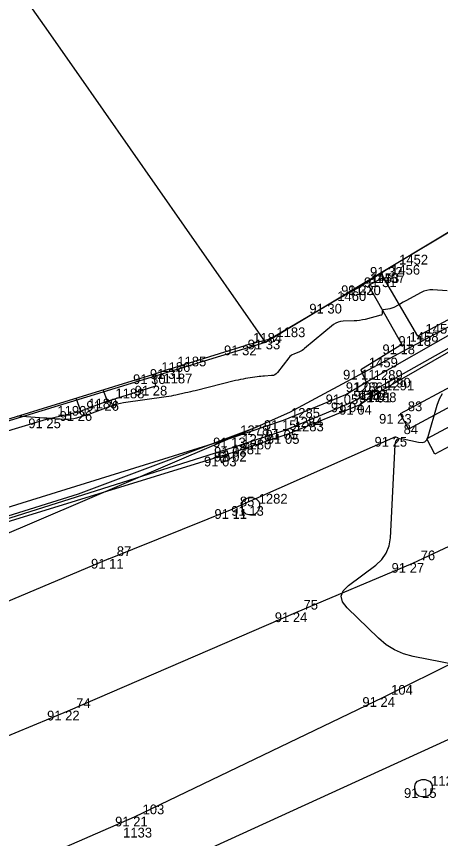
# Model space of a CAD drawing. Extents: x -711081 to -709338, y -1025122 to -1024092.
# Drawn here: x -710971.31 to -710959.11, y -1025043.88 to -1025020.22 of the extents above; entities that cross this region are included whole.
import ezdxf

# ---------------------------------------------------------------- set-up
doc = ezdxf.new("R2010")
doc.units = 0
for name, color, linetype in [('Ex_Minor Contours', 7, 'Continuous'), ('Z_anglicke_dvorky', 7, 'Continuous'), ('Z_body', 7, 'Continuous'), ('Z_body_cisla', 7, 'Continuous'), ('Z_body_vysky_redukovane', 7, 'Continuous'), ('Z_budova', 7, 'Continuous'), ('Z_katastr_hranice', 7, 'Continuous'), ('Z_komunikace', 7, 'Continuous'), ('Z_obruba', 7, 'Continuous'), ('Z_rozhranni', 7, 'Continuous'), ('Z_site_kanalizace_znaky', 7, 'Continuous'), ('Z_vdz12_plna', 7, 'Continuous'), ('Z_vdz12_prerusovana', 7, 'Continuous'), ('Z_vdz25_plna', 7, 'Continuous'), ('Z_vdz25_prerusovana', 7, 'Continuous'), ('Z_vdz_prechod', 7, 'Continuous'), ('Z_vstupy', 7, 'Continuous')]:
    doc.layers.add(name, color=color, linetype=linetype)

# ---------------------------------------------------------------- blocks, each defined once
blk = doc.blocks.new('POINT_DISPLAY')
blk.add_line((0, 0), (0, 0))
blk = doc.blocks.new('Z620')
for p, q in [((-0.17, 0.2), (-0.05, 0.25)), ((-0.05, 0.25), (0.05, 0.25)), ((0.05, 0.25), (0.17, 0.2)), ((-0.25, 0.05), (-0.23, 0.13)), ((-0.25, -0.05), (-0.25, 0.05)), ((-0.23, 0.13), (-0.17, 0.2)), ((0.17, 0.2), (0.23, 0.13)), ((0.23, 0.13), (0.25, 0.05)), ((0.25, 0.05), (0.25, -0.05)), ((-0.2, -0.17), (-0.25, -0.05)), ((-0.13, -0.23), (-0.2, -0.17)), ((-0.05, -0.25), (-0.13, -0.23)), ((0.13, -0.23), (0.05, -0.25)), ((0.2, -0.17), (0.13, -0.23)), ((0.25, -0.05), (0.2, -0.17)), ((0.05, -0.25), (-0.05, -0.25))]:
    blk.add_line(p, q)
blk = doc.blocks.new('Z46260')
for p, q in [((0.13, 0.13), (-0.13, 0.13)), ((-0.13, 0.13), (-0.13, -0.13)), ((0.13, 0), (-0.13, 0)), ((0.13, -0.13), (0.13, 0.13)), ((-0.13, -0.13), (0.13, -0.13))]:
    blk.add_line(p, q)

msp = doc.modelspace()

# ---------------------------------------------------------------- linework, layer by layer
at = {"layer": 'Ex_Minor Contours'}
for points in [[(-710958.915, -1025028.118), (-710959.33, -1025028.091), (-710959.418, -1025028.092), (-710959.505, -1025028.104), (-710959.588, -1025028.129), (-710959.669, -1025028.166), (-710960.107, -1025028.405), (-710960.126, -1025028.415), (-710960.145, -1025028.425), (-710960.163, -1025028.436), (-710960.182, -1025028.446), (-710960.256, -1025028.489), (-710960.275, -1025028.499), (-710960.293, -1025028.51), (-710960.312, -1025028.52), (-710960.331, -1025028.53), (-710960.452, -1025028.593), (-710960.479, -1025028.606), (-710960.507, -1025028.616), (-710960.535, -1025028.625), (-710960.564, -1025028.631), (-710960.745, -1025028.662), (-710960.76, -1025028.667), (-710960.772, -1025028.676), (-710960.779, -1025028.688), (-710960.783, -1025028.704), (-710960.788, -1025028.775), (-710960.791, -1025028.791), (-710960.798, -1025028.803), (-710960.809, -1025028.813), (-710960.824, -1025028.819), (-710961.281, -1025028.938), (-710961.357, -1025028.955), (-710961.435, -1025028.968), (-710961.512, -1025028.977), (-710961.591, -1025028.981), (-710961.906, -1025028.987), (-710961.982, -1025028.995), (-710962.054, -1025029.014), (-710962.122, -1025029.046), (-710962.185, -1025029.09), (-710963.018, -1025029.78), (-710963.053, -1025029.807), (-710963.09, -1025029.831), (-710963.128, -1025029.852), (-710963.169, -1025029.87), (-710963.333, -1025029.938), (-710963.373, -1025029.957), (-710963.409, -1025029.981), (-710963.441, -1025030.009), (-710963.47, -1025030.042), (-710963.8, -1025030.469), (-710963.834, -1025030.505), (-710963.873, -1025030.532), (-710963.918, -1025030.549), (-710963.967, -1025030.557), (-710964.174, -1025030.569), (-710964.225, -1025030.573), (-710964.277, -1025030.578), (-710964.328, -1025030.584), (-710964.379, -1025030.591), (-710964.716, -1025030.644), (-710964.789, -1025030.656), (-710964.862, -1025030.67), (-710964.934, -1025030.685), (-710965.006, -1025030.702), (-710966.166, -1025030.992), (-710966.235, -1025031.009), (-710966.304, -1025031.026), (-710966.373, -1025031.042), (-710966.442, -1025031.057), (-710966.719, -1025031.118), (-710966.789, -1025031.132), (-710966.858, -1025031.145), (-710966.928, -1025031.157), (-710966.999, -1025031.168), (-710968.225, -1025031.344), (-710968.318, -1025031.36), (-710968.411, -1025031.381), (-710968.501, -1025031.407), (-710968.591, -1025031.438), (-710968.974, -1025031.582), (-710969.049, -1025031.61), (-710969.125, -1025031.636), (-710969.2, -1025031.662), (-710969.276, -1025031.686), (-710969.584, -1025031.781), (-710969.659, -1025031.801), (-710969.736, -1025031.814), (-710969.813, -1025031.819), (-710969.89, -1025031.818), (-710970.203, -1025031.799), (-710970.282, -1025031.795), (-710970.36, -1025031.79), (-710970.438, -1025031.785), (-710970.516, -1025031.779), (-710971.27, -1025031.727)], [(-710956.605, -1025039.281), (-710959.896, -1025038.636), (-710960.174, -1025038.561), (-710960.432, -1025038.45), (-710960.67, -1025038.302), (-710960.89, -1025038.117), (-710961.797, -1025037.239), (-710961.927, -1025037.071), (-710961.963, -1025036.908), (-710961.907, -1025036.752), (-710961.756, -1025036.601), (-710960.969, -1025036.011), (-710960.796, -1025035.851), (-710960.668, -1025035.667), (-710960.586, -1025035.458), (-710960.55, -1025035.224), (-710960.412, -1025032.545), (-710960.393, -1025032.45), (-710960.348, -1025032.389), (-710960.277, -1025032.363), (-710960.18, -1025032.372), (-710959.741, -1025032.476), (-710959.641, -1025032.486), (-710959.561, -1025032.461), (-710959.501, -1025032.403), (-710959.461, -1025032.311), (-710959.208, -1025031.405), (-710959.142, -1025031.227), (-710959.049, -1025031.069)]]:
    msp.add_lwpolyline(points, dxfattribs=at)
at = {"layer": 'Z_anglicke_dvorky'}
for p, q in [((-710968.69, -1025031.29), (-710968.818, -1025030.968)), ((-710969.46, -1025031.58), (-710969.587, -1025031.206)), ((-710968.69, -1025031.29), (-710969.46, -1025031.58))]:
    msp.add_line(p, q, dxfattribs=at)
at = {"layer": 'Z_budova'}
for p, q in [((-710951.7, -1025022.12), (-710960.53, -1025027.43)), ((-710960.53, -1025027.43), (-710961.36, -1025027.96)), ((-710964.05, -1025029.52), (-710962.3, -1025028.49)), ((-710964.05, -1025029.52), (-710964.73, -1025029.69)), ((-710966.91, -1025030.37), (-710967.37, -1025030.52)), ((-710967.37, -1025030.52), (-710972.83, -1025032.21))]:
    msp.add_line(p, q, dxfattribs=at)
at = {"layer": 'Z_katastr_hranice'}
for p, q in [((-710970.5, -1025020.49), (-710976.09, -1025012.49)), ((-710969.58, -1025021.8), (-710970.5, -1025020.49)), ((-710964.14, -1025029.59), (-710969.58, -1025021.8)), ((-710964.14, -1025029.59), (-710951.03, -1025021.69)), ((-710955.17, -1025027.15), (-710963.45, -1025031.62)), ((-710979.94, -1025034.42), (-710964.14, -1025029.59)), ((-710963.45, -1025031.62), (-710964.38, -1025032.03)), ((-710964.38, -1025032.03), (-710987.15, -1025041.75)), ((-710969.52, -1025033.96), (-710964.38, -1025032.03)), ((-710998.91, -1025043.08), (-710969.52, -1025033.96)), ((-710988.36, -1025054.5), (-710954.66, -1025039.09))]:
    msp.add_line(p, q, dxfattribs=at)
at = {"layer": 'Z_komunikace'}
for p, q in [((-710961.03, -1025030.98), (-710958.07, -1025029.31)), ((-710961.68, -1025031.33), (-710961.03, -1025030.98)), ((-710963.56, -1025032.12), (-710961.68, -1025031.33)), ((-710965.04, -1025032.61), (-710963.56, -1025032.12)), ((-710972.93, -1025035.1), (-710965.04, -1025032.61))]:
    msp.add_line(p, q, dxfattribs=at)
at = {"layer": 'Z_obruba'}
for p, q in [((-710961.25, -1025030.75), (-710958.28, -1025029.05)), ((-710961.83, -1025031.1), (-710961.25, -1025030.75)), ((-710963.63, -1025031.84), (-710961.83, -1025031.1)), ((-710965.09, -1025032.34), (-710963.63, -1025031.84)), ((-710973.02, -1025034.8), (-710965.09, -1025032.34))]:
    msp.add_line(p, q, dxfattribs=at)
at = {"layer": 'Z_rozhranni'}
for p, q in [((-710960.75, -1025027.73), (-710961.18, -1025027.96)), ((-710959.76, -1025029.42), (-710960.75, -1025027.73)), ((-710961.18, -1025027.96), (-710960.22, -1025029.66)), ((-710958.49, -1025028.73), (-710959.76, -1025029.42)), ((-710960.92, -1025031.05), (-710958.02, -1025029.38)), ((-710960.22, -1025029.66), (-710961.4, -1025030.39)), ((-710961.4, -1025030.39), (-710961.25, -1025030.75)), ((-710967.3, -1025030.85), (-710967.37, -1025030.52)), ((-710968.69, -1025031.29), (-710967.3, -1025030.85)), ((-710961.44, -1025031.4), (-710960.92, -1025031.05)), ((-710970.36, -1025031.79), (-710969.46, -1025031.58)), ((-710963.52, -1025032.24), (-710961.44, -1025031.4)), ((-710970.36, -1025031.79), (-710974.78, -1025033.12)), ((-710965.04, -1025032.75), (-710963.52, -1025032.24)), ((-710972.94, -1025035.19), (-710965.04, -1025032.75))]:
    msp.add_line(p, q, dxfattribs=at)
at = {"layer": 'Z_vdz12_plna'}
for p, q in [((-710959.91, -1025035.95), (-710957.65, -1025034.9)), ((-710963.27, -1025037.37), (-710959.91, -1025035.95))]:
    msp.add_line(p, q, dxfattribs=at)
at = {"layer": 'Z_vdz12_prerusovana'}
for p, q in [((-710969.82, -1025040.2), (-710963.27, -1025037.37)), ((-710974.72, -1025042.24), (-710969.82, -1025040.2))]:
    msp.add_line(p, q, dxfattribs=at)
at = {"layer": 'Z_vdz25_plna'}
msp.add_line((-710960.4, -1025032.32), (-710965.1, -1025034.4), dxfattribs=at)
at = {"layer": 'Z_vdz25_prerusovana'}
for p, q in [((-710968.65, -1025035.83), (-710965.1, -1025034.4)), ((-710968.65, -1025035.83), (-710975.94, -1025038.9)), ((-710960.75, -1025039.81), (-710955.82, -1025037.36)), ((-710967.91, -1025043.25), (-710960.75, -1025039.81)), ((-710975.95, -1025046.75), (-710967.91, -1025043.25))]:
    msp.add_line(p, q, dxfattribs=at)
at = {"layer": 'Z_vdz_prechod'}
for p, q in [((-710956.77, -1025029.77), (-710960.27, -1025031.66)), ((-710956.53, -1025030.21), (-710960.03, -1025032.1)), ((-710956.07, -1025030.53), (-710959.5, -1025032.38)), ((-710955.84, -1025030.97), (-710959.27, -1025032.82)), ((-710960.27, -1025031.66), (-710960.03, -1025032.1)), ((-710959.27, -1025032.82), (-710959.5, -1025032.38))]:
    msp.add_line(p, q, dxfattribs=at)
at = {"layer": 'Z_vstupy'}
for p, q in [((-710962.3, -1025028.49), (-710961.36, -1025027.96)), ((-710966.91, -1025030.37), (-710964.73, -1025029.69))]:
    msp.add_line(p, q, dxfattribs=at)

# ---------------------------------------------------------------- block references
at = {"layer": 'Z_body'}
for p in [(-710960.53, -1025027.43), (-710960.75, -1025027.73), (-710961.36, -1025027.96), (-710961.18, -1025027.96), (-710962.3, -1025028.49), (-710959.76, -1025029.42), (-710964.73, -1025029.69), (-710964.05, -1025029.52), (-710960.22, -1025029.66), (-710966.91, -1025030.37), (-710961.4, -1025030.39), (-710967.37, -1025030.52), (-710967.3, -1025030.85), (-710961.25, -1025030.75), (-710961.83, -1025031.1), (-710961.03, -1025030.98), (-710960.92, -1025031.05), (-710968.69, -1025031.29), (-710961.68, -1025031.33), (-710969.46, -1025031.58), (-710961.44, -1025031.4), (-710970.36, -1025031.79), (-710960.27, -1025031.66), (-710963.63, -1025031.84), (-710963.56, -1025032.12), (-710963.52, -1025032.24), (-710965.09, -1025032.34), (-710960.4, -1025032.32), (-710965.04, -1025032.61), (-710965.04, -1025032.75), (-710965.33, -1025032.89), (-710965.1, -1025034.4), (-710964.57, -1025034.31), (-710968.65, -1025035.83), (-710959.91, -1025035.95), (-710963.27, -1025037.37), (-710960.75, -1025039.81), (-710969.82, -1025040.2), (-710959.6, -1025042.43), (-710967.91, -1025043.25)]:
    msp.add_blockref('POINT_DISPLAY', p, dxfattribs=at)
at = {"layer": 'Z_site_kanalizace_znaky', "rotation": 18}
msp.add_blockref('Z46260', (-710965.33, -1025032.89), dxfattribs=at)
at = {"layer": 'Z_site_kanalizace_znaky'}
for p in [(-710964.57, -1025034.31), (-710959.6, -1025042.43)]:
    msp.add_blockref('Z620', p, dxfattribs=at)

# ---------------------------------------------------------------- texts
at = {"layer": 'Z_body_cisla'}
for s, p in [('1452', (-710960.3, -1025027.36)), ('1456', (-710960.53, -1025027.65)), ('1453', (-710961.13, -1025027.89)), ('1457', (-710960.96, -1025027.89)), ('1460', (-710962.08, -1025028.41)), ('1183', (-710963.83, -1025029.45)), ('1455', (-710959.54, -1025029.35)), ('1184', (-710964.5, -1025029.61)), ('1458', (-710960, -1025029.58)), ('1186', (-710967.14, -1025030.45)), ('1185', (-710966.68, -1025030.29)), ('1459', (-710961.17, -1025030.32)), ('1289', (-710961.03, -1025030.68)), ('1187', (-710967.08, -1025030.78)), ('1290', (-710960.8, -1025030.9)), ('1286', (-710961.6, -1025031.03)), ('1291', (-710960.7, -1025030.98)), ('1188', (-710968.46, -1025031.21)), ('1287', (-710961.46, -1025031.25)), ('1288', (-710961.21, -1025031.32)), ('1189', (-710969.24, -1025031.5)), ('83', (-710960.05, -1025031.58)), ('1190', (-710970.13, -1025031.71)), ('1285', (-710963.41, -1025031.77)), ('1284', (-710963.34, -1025032.04)), ('1278', (-710964.87, -1025032.27)), ('1283', (-710963.3, -1025032.16)), ('84', (-710960.17, -1025032.24)), ('1279', (-710964.81, -1025032.53)), ('1281', (-710965.1, -1025032.82)), ('1280', (-710964.81, -1025032.68)), ('1282', (-710964.34, -1025034.24)), ('85', (-710964.88, -1025034.32)), ('87', (-710968.42, -1025035.75)), ('76', (-710959.68, -1025035.87)), ('75', (-710963.05, -1025037.29)), ('104', (-710960.53, -1025039.74)), ('74', (-710969.59, -1025040.12)), ('1122', (-710959.38, -1025042.36)), ('103', (-710967.68, -1025043.18)), ('1133', (-710968.24, -1025043.85))]:
    msp.add_text(s, height=0.28, dxfattribs=at).set_placement(p)
at = {"layer": 'Z_body_vysky_redukovane'}
for s, p in [('91 32', (-710961.137, -1025027.71)), ('91 31', (-710961.31, -1025028.01)), ('91 32', (-710961.967, -1025028.24)), ('91 30', (-710961.763, -1025028.24)), ('91 30', (-710962.883, -1025028.77)), ('91 18', (-710960.32, -1025029.7)), ('91 32', (-710965.337, -1025029.97)), ('91 33', (-710964.657, -1025029.8)), ('91 18', (-710960.78, -1025029.94)), ('91 31', (-710967.47, -1025030.65)), ('91 11', (-710961.913, -1025030.67)), ('91 30', (-710967.953, -1025030.8)), ('91 28', (-710967.907, -1025031.13)), ('91 03', (-710961.833, -1025031.03)), ('91 05', (-710962.413, -1025031.38)), ('91 02', (-710961.613, -1025031.26)), ('91 01', (-710961.457, -1025031.33)), ('91 26', (-710969.297, -1025031.57)), ('91 04', (-710962.263, -1025031.61)), ('91 26', (-710970.067, -1025031.86)), ('91 04', (-710962.023, -1025031.68)), ('91 25', (-710970.967, -1025032.07)), ('91 23', (-710960.877, -1025031.94)), ('91 15', (-710964.19, -1025032.12)), ('91 05', (-710964.143, -1025032.4)), ('91 05', (-710964.103, -1025032.52)), ('91 13', (-710965.65, -1025032.62)), ('91 25', (-710961.007, -1025032.6)), ('91 03', (-710965.623, -1025032.89)), ('91 02', (-710965.623, -1025033.03)), ('91 03', (-710965.913, -1025033.17)), ('91 11', (-710965.613, -1025034.68)), ('91 13', (-710965.13, -1025034.59)), ('91 11', (-710969.163, -1025036.11)), ('91 27', (-710960.517, -1025036.23)), ('91 24', (-710963.877, -1025037.65)), ('91 24', (-710961.357, -1025040.09)), ('91 22', (-710970.427, -1025040.48)), ('91 15', (-710960.16, -1025042.71)), ('91 21', (-710968.47, -1025043.53))]:
    msp.add_text(s, height=0.28, dxfattribs=at).set_placement(p)

doc.saveas('drawing.dxf')
